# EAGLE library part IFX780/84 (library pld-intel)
PLD
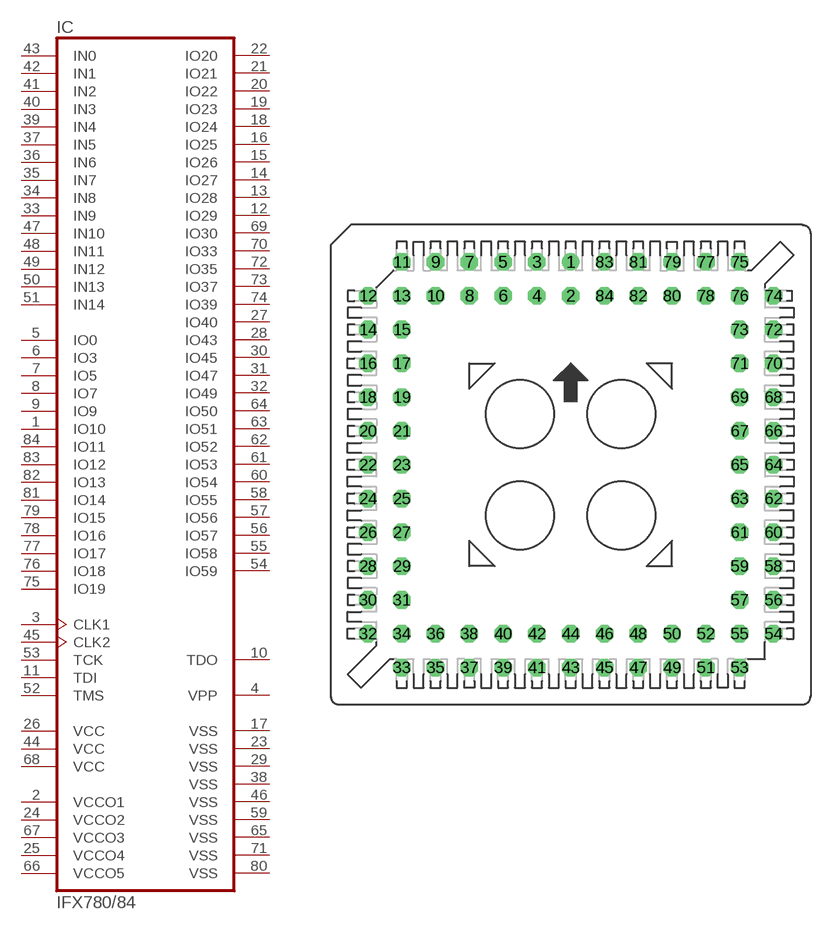
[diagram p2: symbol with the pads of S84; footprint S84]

Designator prefix IC

## IFX780/84 (OC_FARNELL: unknown; OC_NEWARK: unknown)  [S84]
1  IO10
2  VCCO1  sup
3  CLK1  in
4  VPP  sup
5  IO0
6  IO3
7  IO5
8  IO7
9  IO9
10  TDO  out
11  TDI  in
12  IO29
13  IO28
14  IO27
15  IO26
16  IO25
17  VSS  pwr
18  IO24
19  IO23
20  IO22
21  IO21
22  IO20
23  VSS  pwr
24  VCCO2  sup
25  VCCO4  sup
26  VCC  pwr
27  IO40
28  IO43
29  VSS  pwr
30  IO45
31  IO47
32  IO49
33  IN9  in
34  IN8  in
35  IN7  in
36  IN6  in
37  IN5  in
38  VSS  pwr
39  IN4  in
40  IN3  in
41  IN2  in
42  IN1  in
43  IN0  in
44  VCC  pwr
45  CLK2  in
46  VSS  pwr
47  IN10  in
48  IN11  in
49  IN12  in
50  IN13  in
51  IN14  in
52  TMS  in
53  TCK  in
54  IO59
55  IO58
56  IO57
57  IO56
58  IO55
59  VSS  pwr
60  IO54
61  IO53
62  IO52
63  IO51
64  IO50
65  VSS  pwr
66  VCCO5  sup
67  VCCO3  sup
68  VCC  pwr
69  IO30
70  IO33
71  VSS  pwr
72  IO35
73  IO37
74  IO39
75  IO19
76  IO18
77  IO17
78  IO16
79  IO15
80  VSS  pwr
81  IO14
82  IO13
83  IO12
84  IO11

## Footprint S84 (pad centres in mm)
PLCC SOCKET
drill 0.813 round: 1 0,15.24
drill 0.813 octagon: 2 0,12.7; 3 -2.54,15.24; 4 -2.54,12.7; 5 -5.08,15.24; 6 -5.08,12.7; 7 -7.62,15.24; 8 -7.62,12.7; 9 -10.16,15.24; 10 -10.16,12.7; 11 -12.7,15.24; 12 -15.24,12.7; 13 -12.7,12.7; 14 -15.24,10.16; 15 -12.7,10.16; 16 -15.24,7.62; 17 -12.7,7.62; 18 -15.24,5.08; 19 -12.7,5.08; 20 -15.24,2.54; 21 -12.7,2.54; 22 -15.24,0; 23 -12.7,0; 24 -15.24,-2.54; 25 -12.7,-2.54; 26 -15.24,-5.08; 27 -12.7,-5.08; 28 -15.24,-7.62; 29 -12.7,-7.62; 30 -15.24,-10.16; 31 -12.7,-10.16; 32 -15.24,-12.7; 33 -12.7,-15.24; 34 -12.7,-12.7; 35 -10.16,-15.24; 36 -10.16,-12.7; 37 -7.62,-15.24; 38 -7.62,-12.7; 39 -5.08,-15.24; 40 -5.08,-12.7; 41 -2.54,-15.24; 42 -2.54,-12.7; 43 0,-15.24; 44 0,-12.7; 45 2.54,-15.24; 46 2.54,-12.7; 47 5.08,-15.24; 48 5.08,-12.7; 49 7.62,-15.24; 50 7.62,-12.7; 51 10.16,-15.24; 52 10.16,-12.7; 53 12.7,-15.24; 54 15.24,-12.7; 55 12.7,-12.7; 56 15.24,-10.16; 57 12.7,-10.16; 58 15.24,-7.62; 59 12.7,-7.62; 60 15.24,-5.08; 61 12.7,-5.08; 62 15.24,-2.54; 63 12.7,-2.54; 64 15.24,0; 65 12.7,0; 66 15.24,2.54; 67 12.7,2.54; 68 15.24,5.08; 69 12.7,5.08; 70 15.24,7.62; 71 12.7,7.62; 72 15.24,10.16; 73 12.7,10.16; 74 15.24,12.7; 75 12.7,15.24; 76 12.7,12.7; 77 10.16,15.24; 78 10.16,12.7; 79 7.62,15.24; 80 7.62,12.7; 81 5.08,15.24; 82 5.08,12.7; 83 2.54,15.24; 84 2.54,12.7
